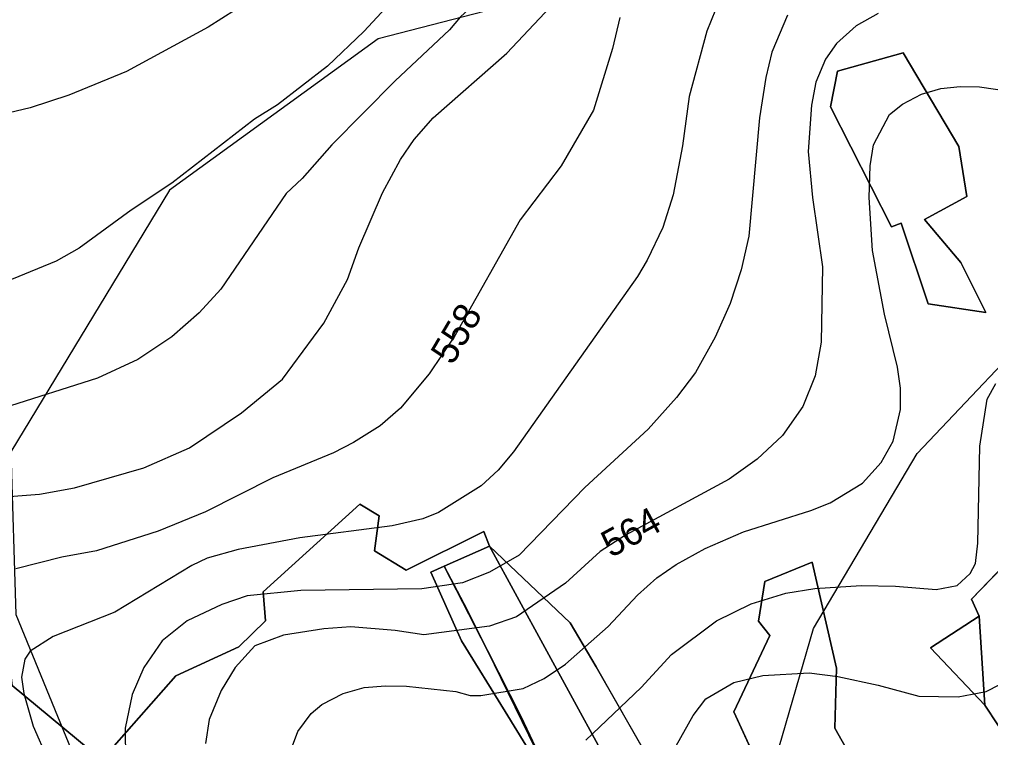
# Model space of a CAD drawing. Extents: x -709418 to -703832, y -1161719 to -1157826.
# Drawn here: x -707302.8 to -707014.5, y -1159133.3 to -1158920.1 of the extents above; entities that cross this region are included whole.
import ezdxf

# ---------------------------------------------------------------- set-up
doc = ezdxf.new("R2010")
doc.units = 0
for name, color, linetype in [('102_obvod PÚ', 7, 'Continuous'), ('120_vrstevnice hlavní', 7, 'Continuous'), ('121_vrstevnice hlavní_popis', 7, 'Continuous'), ('122_vrstevnice základní', 7, 'Continuous'), ('206_TTP_KN', 7, 'Continuous'), ('207_lesní pozemek_KN', 7, 'Continuous'), ('210_ostatní plocha_KN', 7, 'Continuous'), ('514 odvodnění - LPIS', 7, 'Continuous')]:
    doc.layers.add(name, color=color, linetype=linetype)

msp = doc.modelspace()

# ---------------------------------------------------------------- linework, layer by layer
at = {"layer": '102_obvod PÚ'}
for points in [[(-707062.07, -1158946.01), (-707059.97, -1158935.48), (-707040.52, -1158930.02), (-707024, -1158957.85), (-707021.58, -1158972.62), (-707034.17, -1158979.51), (-707023.36, -1158992.21), (-707015.97, -1159007.12), (-707033.1, -1159004.52), (-707041.06, -1158980.54), (-707043.95, -1158981.65), (-707062.07, -1158946.01)], [(-707062.07, -1158946.01), (-707043.95, -1158981.65), (-707041.06, -1158980.54), (-707033.1, -1159004.52), (-707015.97, -1159007.12), (-707023.36, -1158992.21), (-707034.17, -1158979.51), (-707021.58, -1158972.62), (-707024, -1158957.85), (-707040.52, -1158930.02), (-707059.97, -1158935.48), (-707062.07, -1158946.01)], [(-707278.34, -1159139.92), (-707256.39, -1159114.97), (-707237.62, -1159106.3), (-707229.74, -1159098.63), (-707230.46, -1159089.98), (-707201.71, -1159064.02), (-707196.04, -1159067.48), (-707197.43, -1159077.86), (-707188, -1159083.55), (-707164.95, -1159072.1), (-707163.23, -1159076.48), (-707176.75, -1159082.36), (-707163.88, -1159107.46), (-707141.26, -1159153.59)], [(-707141.26, -1159153.59), (-707163.88, -1159107.46), (-707176.75, -1159082.36), (-707163.23, -1159076.48), (-707164.95, -1159072.1), (-707188, -1159083.55), (-707197.43, -1159077.86), (-707196.04, -1159067.48), (-707201.71, -1159064.02), (-707230.46, -1159089.98), (-707229.74, -1159098.63), (-707237.62, -1159106.3), (-707256.39, -1159114.97), (-707278.34, -1159139.92)], [(-707090.72, -1159125.66), (-707080.09, -1159102.97), (-707083.45, -1159098.68), (-707081.52, -1159086.91), (-707067.53, -1159081.2), (-707060.25, -1159112.67), (-707060.75, -1159130.51), (-707056.4, -1159138.22), (-707061.68, -1159151.06), (-707072.46, -1159165.41), (-707090.72, -1159125.66)], [(-707090.72, -1159125.66), (-707072.46, -1159165.41), (-707061.68, -1159151.06), (-707056.4, -1159138.22), (-707060.75, -1159130.51), (-707060.25, -1159112.67), (-707067.53, -1159081.2), (-707081.52, -1159086.91), (-707083.45, -1159098.68), (-707080.09, -1159102.97), (-707090.72, -1159125.66)]]:
    msp.add_lwpolyline(points, dxfattribs=at)
at = {"layer": '120_vrstevnice hlavní'}
for points in [[(-707074.93, -1158795.97), (-707086.28, -1158808.58), (-707096.71, -1158820.86), (-707105.42, -1158830.01), (-707116, -1158839.44), (-707124.43, -1158845.72), (-707133.43, -1158850.58), (-707154.14, -1158863.44), (-707179.57, -1158881.15), (-707197.86, -1158894.72), (-707207, -1158900.58), (-707222.43, -1158908.15), (-707234.57, -1158914.73), (-707246.72, -1158922.44), (-707271, -1158935.58), (-707288.15, -1158942.58), (-707299.58, -1158946.3), (-707316.72, -1158950.44), (-707325.29, -1158951.73), (-707336.72, -1158952.44), (-707345, -1158954.43), (-707352.95, -1158958.19), (-707367.18, -1158970.75), (-707392.01, -1158999.44)], [(-707096.14, -1158917.3), (-707098.71, -1158923.58), (-707104, -1158943.01), (-707106, -1158957.58), (-707108.71, -1158972.16), (-707111.85, -1158981.87), (-707116.43, -1158991.59), (-707119.28, -1158996.44), (-707156.14, -1159048.45), (-707160.71, -1159053.87), (-707165.71, -1159058.59), (-707178.43, -1159066.45), (-707183, -1159068.3), (-707192.14, -1159070.45), (-707219.57, -1159074.02), (-707237.86, -1159077.45), (-707247, -1159080.02), (-707251.58, -1159082.16), (-707274.43, -1159096.02), (-707292.72, -1159103.31), (-707299.58, -1159107.59), (-707301.15, -1159110.02), (-707302.15, -1159115.31), (-707301.43, -1159120.16), (-707298.72, -1159129.88), (-707294.43, -1159139.59)], [(-707107.85, -1159135.74), (-707102.85, -1159126.74), (-707099, -1159121.74), (-707090.71, -1159116.88), (-707082.14, -1159114.88), (-707068.42, -1159114.02), (-707059.85, -1159115.16), (-707047.85, -1159117.74), (-707035.85, -1159121.02), (-707024.14, -1159121.16), (-707015.85, -1159119.59), (-707007.71, -1159115.45)]]:
    msp.add_lwpolyline(points, dxfattribs=at)
at = {"layer": '122_vrstevnice základní'}
for points in [[(-706979.28, -1158768.57), (-707016.99, -1158797.43), (-707051.99, -1158828.86), (-707067.28, -1158841.44), (-707073.57, -1158845.44), (-707099.57, -1158858.44), (-707107.57, -1158863.15), (-707119.57, -1158871.72), (-707131.57, -1158883.15), (-707142.71, -1158892.01), (-707172, -1158919.44), (-707175.14, -1158923.15), (-707191.29, -1158938.3), (-707210, -1158957.3), (-707218.86, -1158967.3), (-707223.57, -1158971.73), (-707243, -1159000.16), (-707249.43, -1159007.16), (-707257.58, -1159014.3), (-707267.58, -1159021.02), (-707279.58, -1159026.59), (-707307.58, -1159035.45)], [(-707160.71, -1158884.19), (-707183.57, -1158905.3), (-707200.57, -1158923.73), (-707211.29, -1158934.01), (-707226.15, -1158945.44), (-707233, -1158949.73), (-707257.58, -1158968.73), (-707269.58, -1158976.73), (-707285.01, -1158988.01), (-707291.86, -1158991.87), (-707310.72, -1158999.59), (-707345.01, -1159007.59), (-707360.44, -1159012.59), (-707372.44, -1159018.87), (-707379.15, -1159024.02), (-707385.01, -1159030.73), (-707390.15, -1159040.73), (-707396.72, -1159063.59), (-707399.44, -1159079.59), (-707399.44, -1159088.16), (-707398.72, -1159094.16), (-707395.01, -1159106.16), (-707391.15, -1159114.16), (-707375.44, -1159135.88)], [(-707325.01, -1159063.16), (-707296.85, -1159061.06), (-707286.43, -1159059.16), (-707265.86, -1159053.16), (-707252.29, -1159047.3), (-707236.86, -1159036.87), (-707224.71, -1159026.91), (-707212.41, -1159010.3), (-707205.43, -1158997.3), (-707202, -1158987.87), (-707195, -1158971.58), (-707189.71, -1158961.73), (-707185.57, -1158955.73), (-707180, -1158949.3), (-707158.14, -1158930.15), (-707142, -1158912.87)], [(-707124.57, -1158919.58), (-707126.71, -1158928.73), (-707132.43, -1158947.01), (-707142, -1158963.58), (-707154.14, -1158979.58), (-707173.43, -1159013.87), (-707181.14, -1159025.3), (-707189.71, -1159035.45), (-707195.72, -1159040.73), (-707203.57, -1159045.73), (-707209.57, -1159048.73), (-707227.57, -1159056.16), (-707247.57, -1159066.3), (-707261.58, -1159072.02), (-707279.86, -1159077.88), (-707290.15, -1159079.73), (-707303.86, -1159083.16)], [(-707074.85, -1158918.87), (-707079.42, -1158929.87), (-707081.28, -1158937.3), (-707083.14, -1158949.3), (-707086.28, -1158984.44), (-707088.57, -1158994.44), (-707091.85, -1159004.44), (-707096.28, -1159014.44), (-707102.14, -1159024.87), (-707107.71, -1159032.3), (-707116.14, -1159041.73), (-707135, -1159059.02), (-707154.43, -1159079.16), (-707163.29, -1159084.16), (-707171.29, -1159087.3), (-707183.29, -1159089.16), (-707219.29, -1159089.59), (-707235.15, -1159091.16), (-707242.72, -1159093.73), (-707253, -1159098.59), (-707260.43, -1159104.59), (-707265.86, -1159112.45), (-707269.29, -1159120.45), (-707271.43, -1159130.45), (-707271.29, -1159139.88)], [(-707047.85, -1158918.3), (-707054.42, -1158922.01), (-707060.28, -1158927.3), (-707063.57, -1158931.87), (-707066.42, -1158938.73), (-707067.71, -1158945.58), (-707068.71, -1158959.3), (-707067.42, -1158973.01), (-707064.42, -1158993.59), (-707064.85, -1159015.87), (-707066.57, -1159025.87), (-707070.28, -1159035.02), (-707076.28, -1159043.59), (-707083.85, -1159050.59), (-707092.14, -1159056.59), (-707122.85, -1159073.16), (-707130.43, -1159078.02), (-707140.71, -1159087.45), (-707155.28, -1159097.45), (-707163.29, -1159100.16), (-707182.71, -1159102.73)], [(-707165.86, -1159120.74), (-707153.28, -1159118.74), (-707147, -1159115.73), (-707140.71, -1159111.45), (-707128, -1159100.31), (-707119.28, -1159091.02), (-707113.57, -1159085.88), (-707107.85, -1159081.88), (-707099.28, -1159077.16), (-707087.85, -1159072.16), (-707067.85, -1159065.88), (-707062.14, -1159063.59), (-707052.57, -1159057.73), (-707046.99, -1159051.59), (-707043.42, -1159045.3), (-707041.28, -1159035.87), (-707041.28, -1159029.59), (-707042.14, -1159023.3), (-707045.99, -1159007.59), (-707049.57, -1158988.73), (-707050.57, -1158973.01), (-707050.28, -1158963.58), (-707049.28, -1158957.3), (-707044.57, -1158948.3), (-707040.71, -1158945.3), (-707034.99, -1158942.3), (-707029.28, -1158940.58), (-707023.56, -1158940.01), (-707017.85, -1158940.15), (-707003.56, -1158942.16)], [(-707134.71, -1159134.02), (-707118.28, -1159118.45), (-707109.28, -1159108.59), (-707095.85, -1159098.59), (-707085.57, -1159093.59), (-707075.28, -1159090.45), (-707066.71, -1159089.02), (-707052.99, -1159088.16), (-707042.71, -1159088.31), (-707030.71, -1159089.3), (-707024.42, -1159088.16), (-707020.56, -1159084.59), (-707018.99, -1159081.59), (-707018.28, -1159075.59), (-707017.71, -1159046.73), (-707015.56, -1159032.87), (-707012.99, -1159028.16)], [(-707182.71, -1159102.73), (-707191.29, -1159101.45), (-707204.43, -1159100.45), (-707212.43, -1159101.02), (-707224.41, -1159102.85), (-707232.86, -1159106.02), (-707238.72, -1159112.45), (-707242.86, -1159119.31), (-707246.43, -1159127.88), (-707247.57, -1159135.02)], [(-707222.29, -1159137.31), (-707220.15, -1159131.45), (-707216.14, -1159126.16), (-707213, -1159123.45), (-707206.72, -1159120.16), (-707200.43, -1159118.45), (-707194.14, -1159117.88), (-707187.86, -1159118.02), (-707173.29, -1159119.59), (-707169, -1159120.74), (-707165.86, -1159120.74)]]:
    msp.add_lwpolyline(points, dxfattribs=at)
at = {"layer": '206_TTP_KN'}
for p, q in [((-707032.35, -1159106.68), (-707017.94, -1159097.19)), ((-707017.94, -1159097.19), (-707016.26, -1159123.62)), ((-707016.26, -1159123.62), (-707032.35, -1159106.68))]:
    msp.add_line(p, q, dxfattribs=at)
for points in [[(-707062.07, -1158946.01), (-707043.95, -1158981.65), (-707041.06, -1158980.54), (-707033.1, -1159004.52), (-707015.97, -1159007.12), (-707023.36, -1158992.21), (-707034.17, -1158979.51), (-707021.58, -1158972.62), (-707024, -1158957.85), (-707040.52, -1158930.02), (-707059.97, -1158935.48), (-707062.07, -1158946.01)], [(-706985.11, -1159055.65), (-707020.15, -1159092.19), (-707017.94, -1159097.19), (-707032.35, -1159106.68), (-707016.26, -1159123.62), (-706985.49, -1159170.3)], [(-707112.14, -1159146.31), (-707131.59, -1159112.27), (-707139.36, -1159099.21), (-707163.23, -1159076.48), (-707164.95, -1159072.1), (-707188, -1159083.55), (-707197.43, -1159077.86), (-707196.04, -1159067.48), (-707201.71, -1159064.02), (-707230.46, -1159089.98), (-707229.74, -1159098.63), (-707237.62, -1159106.3), (-707256.39, -1159114.97), (-707278.34, -1159139.92), (-707304.89, -1159117.79)], [(-707141.26, -1159153.59), (-707153.99, -1159126.87), (-707163.88, -1159107.46), (-707170.87, -1159093.47), (-707176.75, -1159082.36), (-707163.23, -1159076.48), (-707130.37, -1159136.64)], [(-707090.72, -1159125.66), (-707072.46, -1159165.41), (-707061.68, -1159151.06), (-707056.4, -1159138.22), (-707060.75, -1159130.51), (-707060.25, -1159112.67), (-707067.53, -1159081.2), (-707081.52, -1159086.91), (-707083.45, -1159098.68), (-707080.09, -1159102.97), (-707090.72, -1159125.66)]]:
    msp.add_lwpolyline(points, dxfattribs=at)
at = {"layer": '207_lesní pozemek_KN'}
for p, q in [((-707059.97, -1158935.48), (-707040.52, -1158930.02)), ((-707040.52, -1158930.02), (-707024, -1158957.85)), ((-707062.07, -1158946.01), (-707059.97, -1158935.48)), ((-707043.95, -1158981.65), (-707062.07, -1158946.01)), ((-707024, -1158957.85), (-707021.58, -1158972.62)), ((-707021.58, -1158972.62), (-707034.17, -1158979.51)), ((-707034.17, -1158979.51), (-707023.36, -1158992.21)), ((-707041.06, -1158980.54), (-707043.95, -1158981.65)), ((-707033.1, -1159004.52), (-707041.06, -1158980.54)), ((-707023.36, -1158992.21), (-707015.97, -1159007.12)), ((-707015.97, -1159007.12), (-707033.1, -1159004.52)), ((-707230.46, -1159089.98), (-707201.71, -1159064.02)), ((-707201.71, -1159064.02), (-707196.04, -1159067.48)), ((-707196.04, -1159067.48), (-707197.43, -1159077.86)), ((-707188, -1159083.55), (-707164.95, -1159072.1)), ((-707164.95, -1159072.1), (-707163.23, -1159076.48)), ((-707197.43, -1159077.86), (-707188, -1159083.55)), ((-707163.23, -1159076.48), (-707176.75, -1159082.36)), ((-707163.23, -1159076.48), (-707139.36, -1159099.21)), ((-707130.37, -1159136.64), (-707163.23, -1159076.48)), ((-707176.75, -1159082.36), (-707180.65, -1159084.18)), ((-707180.65, -1159084.18), (-707176.75, -1159082.36)), ((-707176.75, -1159082.36), (-707170.87, -1159093.47)), ((-707081.52, -1159086.91), (-707067.53, -1159081.2)), ((-707067.53, -1159081.2), (-707060.25, -1159112.67)), ((-707180.65, -1159084.18), (-707171.58, -1159104.53)), ((-707171.58, -1159104.53), (-707180.65, -1159084.18)), ((-707083.45, -1159098.68), (-707081.52, -1159086.91)), ((-707229.74, -1159098.63), (-707230.46, -1159089.98)), ((-707170.87, -1159093.47), (-707163.88, -1159107.46)), ((-707237.62, -1159106.3), (-707229.74, -1159098.63)), ((-707139.36, -1159099.21), (-707131.59, -1159112.27)), ((-707080.09, -1159102.97), (-707083.45, -1159098.68)), ((-707090.72, -1159125.66), (-707080.09, -1159102.97)), ((-707256.39, -1159114.97), (-707237.62, -1159106.3)), ((-707171.58, -1159104.53), (-707158.63, -1159125.51)), ((-707158.63, -1159125.51), (-707171.58, -1159104.53)), ((-707163.88, -1159107.46), (-707153.99, -1159126.87)), ((-707131.59, -1159112.27), (-707112.14, -1159146.31)), ((-707060.25, -1159112.67), (-707060.75, -1159130.51)), ((-707278.34, -1159139.92), (-707256.39, -1159114.97)), ((-707158.63, -1159125.51), (-707141.26, -1159153.59)), ((-707141.26, -1159153.59), (-707158.63, -1159125.51)), ((-707153.99, -1159126.87), (-707141.26, -1159153.59)), ((-707072.46, -1159165.41), (-707090.72, -1159125.66)), ((-707060.75, -1159130.51), (-707056.4, -1159138.22))]:
    msp.add_line(p, q, dxfattribs=at)
at = {"layer": '210_ostatní plocha_KN'}
for p, q in [((-707020.15, -1159092.19), (-706985.11, -1159055.65)), ((-707017.94, -1159097.19), (-707020.15, -1159092.19)), ((-707016.26, -1159123.62), (-707017.94, -1159097.19)), ((-706985.49, -1159170.3), (-707016.26, -1159123.62))]:
    msp.add_line(p, q, dxfattribs=at)
msp.add_lwpolyline([(-707419.71, -1159142.98), (-707395.02, -1159109.23), (-707384.1, -1159069.77), (-707374.68, -1159048.22), (-707374.15, -1159072.35), (-707380.86, -1159087.33), (-707382.36, -1159101.36), (-707393.49, -1159116.45), (-707389.96, -1159123.69), (-707375.22, -1159099.68), (-707365.61, -1159072.61), (-707368.54, -1159044.01), (-707357.62, -1159066.06), (-707352.48, -1159072.7), (-707318.02, -1159077.05), (-707308.6, -1159090.75), (-707304.89, -1159117.79), (-707278.34, -1159139.92)], dxfattribs=at)
at = {"layer": '514 odvodnění - LPIS'}
for points in [[(-707091.66, -1159185.61), (-707067.05, -1159100.92), (-707036.31, -1159048.98), (-706995.04, -1159005.45), (-706934.01, -1159011.63), (-706947.99, -1159058.39), (-706922.15, -1159060.93), (-706851.26, -1159022.69), (-706790.89, -1158973.74), (-706747.02, -1158912.58), (-706716.93, -1158759.9), (-706697.06, -1158726.14), (-706670.64, -1158725.93), (-706602.78, -1158847.92), (-706583.04, -1158891.24), (-706552.73, -1158910.18), (-706494.68, -1158910.47), (-706457.47, -1158890.53), (-706273.62, -1158913.9)], [(-707497.47, -1159147.65), (-707457.12, -1159066.36), (-707381.61, -1158936.97), (-707303.69, -1158878.31), (-707096.69, -1158824.65), (-707088.79, -1158844.54), (-707098.48, -1158900.51), (-707196.29, -1158925.83), (-707258.23, -1158970.76), (-707305.34, -1159048.43), (-707303.87, -1159096.76), (-707286.56, -1159139.02)]]:
    msp.add_lwpolyline(points, dxfattribs=at)

# ---------------------------------------------------------------- texts
at = {"layer": '121_vrstevnice hlavní_popis'}
for s, rotation, p in [('558', 59.3681, (-707174.25, -1159023.01)), ('564', 28.6821, (-707127.22, -1159080.04))]:
    msp.add_text(s, height=8, rotation=rotation, dxfattribs=at).set_placement(p)

doc.saveas('drawing.dxf')
